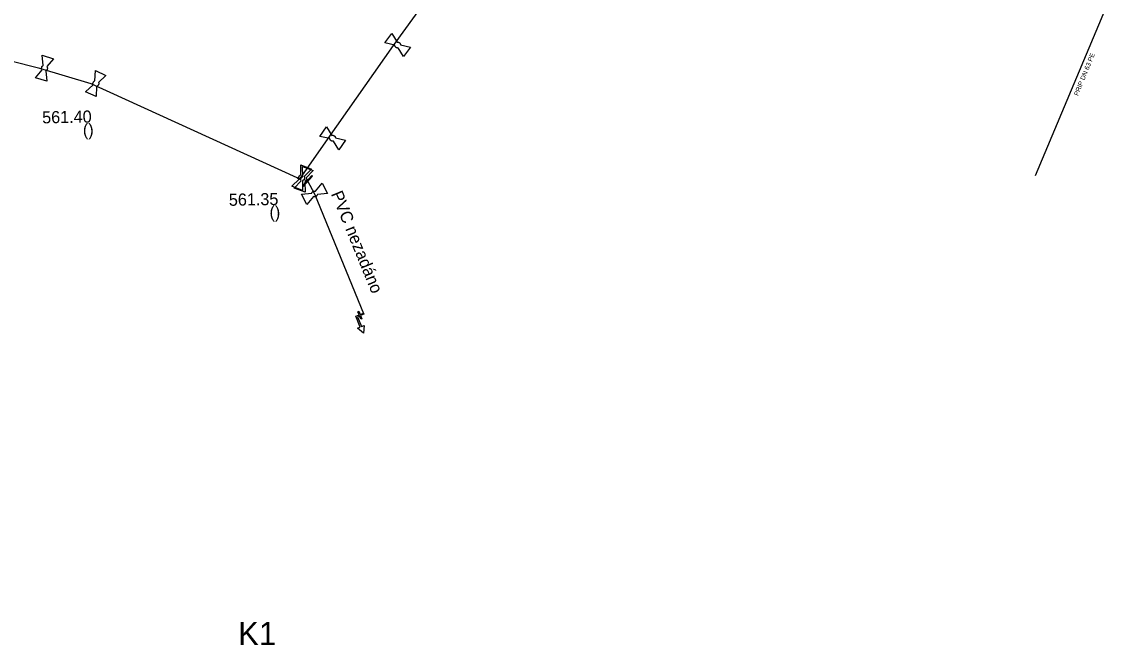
# Model space of a CAD drawing. Extents: x -643544 to -637295, y -1119190 to -1111715.
# Drawn here: x -642912.6 to -642795.2, y -1114466.3 to -1114399.3 of the extents above; entities that cross this region are included whole.
import ezdxf

# ---------------------------------------------------------------- set-up
doc = ezdxf.new("R2010")
doc.units = 0
for name, color, linetype in [('Default', 7, 'Continuous'), ('VP Hydrant', 7, 'Continuous'), ('VP Lomový bod', 7, 'Continuous'), ('VP Lomový bod - popis', 7, 'Continuous'), ('VP Popis nerozlišený', 7, 'Continuous'), ('VP Popis přípojky', 7, 'Continuous'), ('VP Přípojka', 7, 'Continuous'), ('VP Řad', 7, 'Continuous'), ('VP Řad - popis', 7, 'Continuous'), ('VP Šoupě', 7, 'Continuous')]:
    doc.layers.add(name, color=color, linetype=linetype)

msp = doc.modelspace()

# ---------------------------------------------------------------- linework, layer by layer
at = {"layer": 'Default'}
for points in [[(-642872.17, -1114402.13), (-642872.22, -1114402.15), (-642872.27, -1114402.14), (-642872.36, -1114402.13), (-642872.42, -1114402.08), (-642872.49, -1114402.03), (-642872.53, -1114401.96), (-642872.55, -1114401.91), (-642872.55, -1114401.85)], [(-642872.31, -1114401.52), (-642872.26, -1114401.51), (-642872.21, -1114401.52), (-642872.12, -1114401.53), (-642872.06, -1114401.58), (-642871.99, -1114401.63), (-642871.96, -1114401.7), (-642871.93, -1114401.75), (-642871.93, -1114401.8)], [(-642910.41, -1114404.48), (-642910.44, -1114404.43), (-642910.45, -1114404.38), (-642910.47, -1114404.3), (-642910.45, -1114404.22), (-642910.43, -1114404.14), (-642910.36, -1114404.08), (-642910.33, -1114404.04), (-642910.28, -1114404.02)], [(-642909.89, -1114404.14), (-642909.86, -1114404.18), (-642909.85, -1114404.24), (-642909.83, -1114404.32), (-642909.85, -1114404.4), (-642909.87, -1114404.48), (-642909.93, -1114404.54), (-642909.97, -1114404.57), (-642910.02, -1114404.6)], [(-642904.92, -1114406.09), (-642904.95, -1114406.04), (-642904.95, -1114405.99), (-642904.96, -1114405.9), (-642904.92, -1114405.83), (-642904.89, -1114405.76), (-642904.82, -1114405.7), (-642904.78, -1114405.67), (-642904.73, -1114405.66)], [(-642904.35, -1114405.83), (-642904.33, -1114405.88), (-642904.33, -1114405.93), (-642904.32, -1114406.02), (-642904.36, -1114406.09), (-642904.39, -1114406.16), (-642904.46, -1114406.21), (-642904.5, -1114406.25), (-642904.55, -1114406.26)], [(-642879.14, -1114412.13), (-642879.19, -1114412.15), (-642879.25, -1114412.14), (-642879.33, -1114412.13), (-642879.4, -1114412.09), (-642879.47, -1114412.04), (-642879.5, -1114411.96), (-642879.53, -1114411.91), (-642879.53, -1114411.86)], [(-642879.3, -1114411.53), (-642879.25, -1114411.51), (-642879.19, -1114411.52), (-642879.11, -1114411.53), (-642879.04, -1114411.57), (-642878.97, -1114411.62), (-642878.94, -1114411.7), (-642878.91, -1114411.75), (-642878.91, -1114411.8)], [(-642882.82, -1114416.21), (-642882.84, -1114416.16), (-642882.85, -1114416.11), (-642882.86, -1114416.03), (-642882.83, -1114415.95), (-642882.8, -1114415.87), (-642882.73, -1114415.82), (-642882.69, -1114415.79), (-642882.64, -1114415.77)], [(-642882.6, -1114416.4), (-642882.62, -1114416.36), (-642882.63, -1114416.3), (-642882.64, -1114416.22), (-642882.61, -1114416.14), (-642882.58, -1114416.06), (-642882.52, -1114416.01), (-642882.48, -1114415.97), (-642882.43, -1114415.96)], [(-642882.26, -1114415.93), (-642882.24, -1114415.98), (-642882.23, -1114416.03), (-642882.22, -1114416.11), (-642882.25, -1114416.19), (-642882.28, -1114416.27), (-642882.35, -1114416.32), (-642882.39, -1114416.35), (-642882.44, -1114416.37)], [(-642882.05, -1114416.1), (-642882.02, -1114416.15), (-642882.01, -1114416.2), (-642882, -1114416.28), (-642882.03, -1114416.36), (-642882.06, -1114416.44), (-642882.12, -1114416.49), (-642882.16, -1114416.53), (-642882.21, -1114416.54)], [(-642881.47, -1114417.74), (-642881.46, -1114417.69), (-642881.43, -1114417.64), (-642881.39, -1114417.57), (-642881.32, -1114417.53), (-642881.24, -1114417.5), (-642881.16, -1114417.5), (-642881.1, -1114417.5), (-642881.05, -1114417.52)], [(-642880.86, -1114417.88), (-642880.88, -1114417.93), (-642880.9, -1114417.98), (-642880.95, -1114418.05), (-642881.02, -1114418.09), (-642881.1, -1114418.12), (-642881.18, -1114418.12), (-642881.23, -1114418.12), (-642881.28, -1114418.1)]]:
    msp.add_open_spline(points, degree=3, dxfattribs=at)
at = {"layer": 'VP Hydrant'}
msp.add_lwpolyline([(-642876.33, -1114430.91), (-642876.56, -1114431.01), (-642876.14, -1114432.05), (-642875.85, -1114431.93), (-642875.92, -1114432.77), (-642876.55, -1114432.22), (-642876.25, -1114432.1), (-642876.73, -1114430.94), (-642876.38, -1114430.8), (-642876.52, -1114430.46), (-642876.41, -1114430.41), (-642876.27, -1114430.75), (-642875.92, -1114430.61), (-642875.87, -1114430.73), (-642876.22, -1114430.87), (-642876.08, -1114431.21), (-642876.19, -1114431.26), (-642876.33, -1114430.91)], dxfattribs=at)
at = {"layer": 'VP Lomový bod'}
for points in [[(-642873.62, -1114401.6), (-642872.88, -1114400.59), (-642872.31, -1114401.52)], [(-642872.55, -1114401.85), (-642873.62, -1114401.6)], [(-642871.93, -1114401.8), (-642870.86, -1114402.06), (-642871.6, -1114403.07), (-642872.17, -1114402.13)], [(-642910.39, -1114402.93), (-642909.19, -1114403.29), (-642909.89, -1114404.14)], [(-642910.28, -1114404.02), (-642910.39, -1114402.93)], [(-642910.02, -1114404.6), (-642909.91, -1114405.69), (-642911.11, -1114405.33), (-642910.41, -1114404.48)], [(-642904.73, -1114405.66), (-642904.69, -1114404.56)], [(-642904.69, -1114404.56), (-642903.55, -1114405.08), (-642904.35, -1114405.83)], [(-642904.55, -1114406.26), (-642904.59, -1114407.36), (-642905.73, -1114406.84), (-642904.92, -1114406.09)], [(-642880.6, -1114411.63), (-642879.89, -1114410.6), (-642879.3, -1114411.53)], [(-642879.53, -1114411.86), (-642880.6, -1114411.63)], [(-642878.91, -1114411.8), (-642877.84, -1114412.03), (-642878.55, -1114413.06), (-642879.14, -1114412.13)], [(-642882.64, -1114415.77), (-642882.64, -1114414.68), (-642881.48, -1114415.15), (-642882.26, -1114415.93)], [(-642882.43, -1114415.96), (-642882.47, -1114414.86), (-642881.3, -1114415.3), (-642882.05, -1114416.1)], [(-642882.44, -1114417.46), (-642883.6, -1114416.99), (-642882.82, -1114416.21)], [(-642882.17, -1114417.64), (-642883.34, -1114417.2), (-642882.6, -1114416.4)], [(-642882.44, -1114416.37), (-642882.44, -1114417.46)], [(-642882.21, -1114416.54), (-642882.17, -1114417.64)], [(-642881.28, -1114418.1), (-642881.98, -1114418.95), (-642882.57, -1114417.84), (-642881.47, -1114417.74)], [(-642881.05, -1114417.52), (-642880.36, -1114416.67)], [(-642880.36, -1114416.67), (-642879.77, -1114417.78), (-642880.86, -1114417.88)]]:
    msp.add_lwpolyline(points, dxfattribs=at)
at = {"layer": 'VP Přípojka'}
msp.add_lwpolyline([(-642795.23, -1114395.39), (-642803.82, -1114415.88)], dxfattribs=at)
at = {"layer": 'VP Řad'}
for points in [[(-642844.45, -1114369.35), (-642844.55, -1114369.77), (-642844.88, -1114370.12), (-642845.43, -1114371.16), (-642846.99, -1114374.27), (-642851.67, -1114385.88), (-642851.85, -1114386.55), (-642852.38, -1114386.77), (-642855.69, -1114385.36), (-642859.68, -1114383.66), (-642860.09, -1114383.81), (-642860.38, -1114384.31), (-642863.26, -1114388.82), (-642872.74, -1114401.86), (-642879.72, -1114411.86), (-642882.82, -1114416.28), (-642883.04, -1114416.1), (-642905.14, -1114405.99), (-642910.65, -1114404.34), (-642917.33, -1114402.66)], [(-642882.32, -1114416.25), (-642881.91, -1114416.41), (-642881.17, -1114417.81), (-642875.91, -1114430.64)]]:
    msp.add_lwpolyline(points, dxfattribs=at)
at = {"layer": 'VP Šoupě'}
msp.add_lwpolyline([(-642882.45, -1114416.93), (-642881.44, -1114415.82), (-642881.37, -1114415.89), (-642882.38, -1114417), (-642882.45, -1114416.93)], dxfattribs=at)

# ---------------------------------------------------------------- texts
at = {"layer": 'VP Lomový bod - popis'}
for s, p in [('561.40', (-642910.39, -1114410.24)), ('()', (-642906.02, -1114411.57)), ('561.35', (-642890.35, -1114419.09)), ('()', (-642885.99, -1114420.41))]:
    msp.add_text(s, height=1.3, rotation=1, dxfattribs=at).set_placement(p)
at = {"layer": 'VP Popis nerozlišený'}
msp.add_text('K1', height=2.5, dxfattribs=at).set_placement((-642889.37, -1114466.26))
at = {"layer": 'VP Popis přípojky'}
msp.add_text('PRIP DN 63 PE', height=0.5, rotation=68.0444, dxfattribs=at).set_placement((-642799.21, -1114407.32))
at = {"layer": 'VP Řad - popis'}
msp.add_text('PVC nezadáno', height=1.3, rotation=292.2925, dxfattribs=at).set_placement((-642879.42, -1114417.8))

doc.saveas('drawing.dxf')
